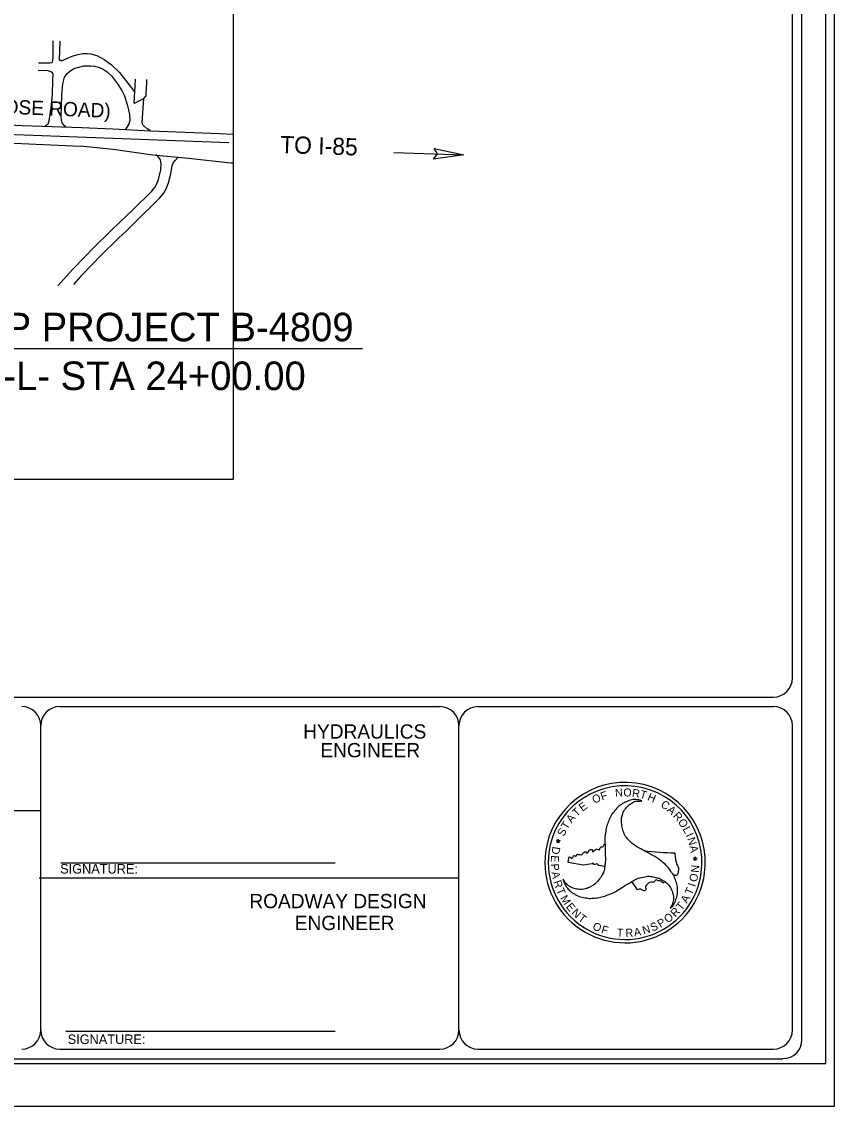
# Model space of a CAD drawing. Extents: x 1530800 to 1534168, y 642962 to 645162.
# Drawn here: x 1533314 to 1534168, y 642962 to 644102 of the extents above; entities that cross this region are included whole.
import ezdxf

# ---------------------------------------------------------------- set-up
doc = ezdxf.new("R2010")
doc.units = 0
for name, color, linetype in [('Exist Roads EOP', 7, 'Continuous'), ('Exist Roads EOP Other', 7, 'Continuous'), ('Exist Roads Soil', 7, 'Continuous'), ('Old_Level_1', 7, 'Continuous'), ('Old_Level_11', 7, 'Continuous'), ('Old_Level_6', 7, 'Continuous'), ('Prop Horizontal Alignment', 7, 'Continuous'), ('Sheet Cutting Line CELL', 7, 'Continuous'), ('Sheet Plot Border Inside CELL', 7, 'Continuous'), ('Sheet Plot Border Outside CELL', 7, 'Continuous'), ('Sheet Title CELL', 7, 'Continuous')]:
    doc.layers.add(name, color=color, linetype=linetype)

msp = doc.modelspace()

# ---------------------------------------------------------------- linework, layer by layer
at = {"layer": 'Exist Roads EOP'}
for points in [[(1532837.2, 644011.2), (1532887.5, 644009), (1532932.2, 644007.8), (1532979.1, 644006), (1533024.3, 644004.3), (1533074.5, 644002.6), (1533122.3, 644001), (1533169.2, 643999.2), (1533215.3, 643997.3), (1533264.8, 643995.5), (1533315, 643993.2), (1533377.5, 643991.1)], [(1532836.8, 643992.3), (1532887, 643990.3), (1532930.7, 643988.8), (1532978.4, 643986.9), (1533023.5, 643984.9), (1533074.4, 643983.4), (1533120.9, 643981.7), (1533167.8, 643979.8), (1533215.1, 643978), (1533262.8, 643975.9), (1533314, 643974.1), (1533375.9, 643971.4)], [(1533377.5, 643991.1), (1533410.3, 643989.6), (1533449.9, 643987.5)], [(1533449.9, 643987.5), (1533486.1, 643985.9), (1533522.3, 643984.7), (1533535.8, 643984)], [(1533535.8, 643984), (1533535.8, 643984)], [(1533536.6, 643953.4), (1533534, 643953.6), (1533489.7, 643958.4), (1533452.1, 643961.8), (1533410.6, 643967.7), (1533375.9, 643971.4)], [(1533478.9, 643959.8), (1533478.9, 643959.8)]]:
    msp.add_lwpolyline(points, dxfattribs=at)
at = {"layer": 'Exist Roads EOP Other'}
for points in [[(1533432.7, 644016.4), (1533433.6, 644034.9), (1533434, 644041.9)], [(1533442.6, 644021.5), (1533445.2, 644024.1), (1533445.4, 644035.2)], [(1533445.4, 644041.5), (1533445.4, 644035.2)], [(1533438.4, 644019.3), (1533442.6, 644021.5)], [(1533432.7, 644016.4), (1533432.9, 644016.4), (1533438.4, 644019.3)], [(1533535.8, 643984), (1533536.6, 643984.4)], [(1533433.4, 643891.1), (1533459.3, 643916.6), (1533463.4, 643921.6), (1533466.2, 643926.4), (1533468.6, 643932.9), (1533471, 643942.2), (1533471.8, 643946.9), (1533472.6, 643950.6), (1533473.9, 643954.1), (1533475.9, 643956.7), (1533478.9, 643959.8)], [(1533457.8, 643960), (1533455.5, 643962.4)], [(1533458, 643936.2), (1533460.5, 643946.6), (1533460.8, 643952.8), (1533460.2, 643956.9), (1533459.1, 643958.5), (1533457.8, 643960)], [(1533431.2, 643904.5), (1533451, 643924.1), (1533454.2, 643928), (1533456.1, 643931.2), (1533458, 643936.2)], [(1533425, 643898.4), (1533408.6, 643883), (1533388.7, 643863.5), (1533381.4, 643855.9), (1533367.8, 643841.8), (1533352.5, 643824.6)], [(1533425, 643898.4), (1533431.2, 643904.5)], [(1533424, 643882.1), (1533433.4, 643891.1)], [(1533424, 643882.1), (1533416.4, 643874.9), (1533396.7, 643855.6), (1533389.5, 643848.1), (1533376, 643834.2), (1533368.8, 643826.1)]]:
    msp.add_lwpolyline(points, dxfattribs=at)
at = {"layer": 'Exist Roads Soil'}
for points in [[(1533346.4, 644059.1), (1533346.9, 644060), (1533347.2, 644061.3), (1533347.5, 644065.9), (1533347.6, 644081.9)], [(1533355.9, 644061.2), (1533355.4, 644061.3), (1533354.7, 644061.5), (1533354.2, 644061.9), (1533354.8, 644081.7)], [(1533355.9, 644061.2), (1533357.8, 644061.9), (1533363.1, 644064.2), (1533368.6, 644066.3), (1533373.7, 644067.8), (1533378.6, 644068.8), (1533383.2, 644068.9), (1533386.9, 644068.5), (1533393.3, 644066.6), (1533401.2, 644062.4), (1533408.3, 644057.3), (1533417, 644048.7), (1533423.5, 644040.6), (1533428.2, 644034.5), (1533432.5, 644028.8)], [(1533332, 644059), (1533344, 644058.8), (1533346.4, 644059.1)], [(1533369.1, 644052.8), (1533374.4, 644054.3), (1533379.8, 644055.6), (1533383.5, 644055.9), (1533387, 644055.7), (1533391, 644055.3), (1533396.2, 644053.9), (1533399.9, 644052.4), (1533404.3, 644049.4), (1533408.7, 644045.4)], [(1533346.8, 644025.8), (1533347.2, 644041.1), (1533347.4, 644046.8), (1533346.7, 644048.3), (1533344.9, 644049.6), (1533342.1, 644050.5), (1533331.7, 644051)], [(1533360.8, 643991.8), (1533359.2, 643992.6), (1533357.9, 643994.3), (1533356.9, 643996), (1533356.3, 643998.4), (1533356, 644002.5), (1533356.5, 644024.9), (1533357.5, 644036.7), (1533359.3, 644043.8), (1533361.9, 644047.3), (1533364.6, 644049.9), (1533369.1, 644052.8)], [(1533408.7, 644045.4), (1533415.2, 644036.9), (1533419.6, 644029.7), (1533422.6, 644023.6)], [(1533339.2, 643992.6), (1533342.2, 643994.7), (1533343.4, 643998.1), (1533345.5, 644012), (1533346.8, 644025.8)], [(1533423.4, 643988.9), (1533425, 643990.6), (1533426.8, 643994), (1533428.2, 643998.7), (1533427.9, 644004.6), (1533425.8, 644013.8), (1533422.6, 644023.6)], [(1533432.5, 644028.8), (1533433, 644028.1)], [(1533449.9, 643987.5), (1533446.4, 643989.5), (1533443.2, 643992.5), (1533441.8, 643993.9), (1533441.2, 643995.1), (1533440.9, 643996.2), (1533442.6, 644021.5)]]:
    msp.add_lwpolyline(points, dxfattribs=at)
at = {"layer": 'Old_Level_1'}
for p, q in [((1533705.6, 643964.8), (1533779.1, 643962.3)), ((1533672.5, 643758.2), (1533152.9, 643758.2))]:
    msp.add_line(p, q, dxfattribs=at)
at = {"layer": 'Old_Level_11'}
msp.add_lwpolyline([(1533747.8, 643968.8), (1533779.1, 643962.3), (1533747.2, 643957.8), (1533751.4, 643963.2)], close=True, dxfattribs=at)
at = {"layer": 'Old_Level_6'}
msp.add_lwpolyline([(1531841.4, 644402.1), (1533536.6, 644402.1), (1533536.6, 643621.2), (1531841.4, 643621.2)], close=True, dxfattribs=at)
at = {"layer": 'Prop Horizontal Alignment'}
msp.add_line((1531841.4, 644038.2), (1533531.9, 643975.1), dxfattribs=at)
at = {"layer": 'Sheet Cutting Line CELL'}
msp.add_line((1530800.4, 642962.3), (1534168.4, 642962.3), dxfattribs=at)
at = {"layer": 'Sheet Plot Border Inside CELL'}
msp.add_lwpolyline([(1530826.4, 643007.2), (1534159.4, 643007.2), (1534159.4, 645117.4), (1530826.4, 645117.4)], close=True, dxfattribs=at)
at = {"layer": 'Sheet Plot Border Outside CELL'}
for p, q in [((1534168.4, 642962.3), (1534168.4, 645162.3)), ((1530800.4, 642962.3), (1534168.4, 642962.3))]:
    msp.add_line(p, q, dxfattribs=at)
at = {"layer": 'Sheet Title CELL'}
for p, q in [((1531264.4, 643392.3), (1534104.4, 643392.3)), ((1533354.4, 643382.3), (1533753.9, 643382.3)), ((1533793.9, 643382.3), (1534104.4, 643382.3)), ((1533334.4, 643042.3), (1533334.4, 643362.3)), ((1533773.9, 643042.3), (1533773.9, 643362.3)), ((1533966.2, 643283.5), (1533966, 643283.4)), ((1533966.2, 643283.5), (1533966, 643283.4)), ((1533334.4, 643272.8), (1532724.4, 643272.8)), ((1533877.3, 643241), (1533876.3, 643242)), ((1533876.3, 643242), (1533877.7, 643241.8)), ((1533876.7, 643239.6), (1533877.3, 643241)), ((1533878, 643240.3), (1533876.7, 643239.6)), ((1533877.7, 643241.8), (1533878.3, 643243.1)), ((1533879, 643239.3), (1533878, 643240.3)), ((1533878.3, 643243.1), (1533878.6, 643241.7)), ((1533878.6, 643241.7), (1533880.1, 643241.5)), ((1533880.1, 643241.5), (1533878.8, 643240.8)), ((1533878.8, 643240.8), (1533879, 643239.3)), ((1533888.5, 643218.4), (1533889.4, 643223.4)), ((1533968.3, 643231), (1533968.3, 643231)), ((1534021.8, 643223.1), (1534020.4, 643223.3)), ((1534020.4, 643223.3), (1534021.5, 643222.3)), ((1534022.5, 643224.4), (1534021.8, 643223.1)), ((1534022.8, 643223), (1534022.5, 643224.4)), ((1534024.2, 643222.8), (1534022.8, 643223)), ((1534022.9, 643222.1), (1534024.2, 643222.8)), ((1533355.4, 643218.3), (1533643.9, 643218.3)), ((1533904.3, 643215.7), (1533888.5, 643218.4)), ((1533913.8, 643217.2), (1533904.3, 643215.7)), ((1533927.2, 643214.3), (1533920.6, 643215.2)), ((1534021.5, 643222.3), (1534020.9, 643220.9)), ((1534020.9, 643220.9), (1534022.1, 643221.6)), ((1534022.1, 643221.6), (1534023.1, 643220.6)), ((1534023.1, 643220.6), (1534022.9, 643222.1)), ((1533332.6, 643202.3), (1533773.9, 643202.3)), ((1534032.1, 643207.3), (1534032.1, 643207.3)), ((1533961.6, 643189.9), (1533955.6, 643198.5)), ((1533955.6, 643198.5), (1533955.6, 643198.5)), ((1533360.9, 643041.2), (1533643.9, 643041.2))]:
    msp.add_line(p, q, dxfattribs=at)
for points in [[(1534134.4, 643032.3), (1534134.4, 645092.3)], [(1534124.4, 643412.3), (1534124.4, 645082.3)], [(1534124.4, 643042.3), (1534124.4, 643362.3)], [(1533354.4, 643022.3), (1533753.9, 643022.3)], [(1533793.9, 643022.3), (1534104.4, 643022.3)], [(1531154.4, 643012.3), (1534114.4, 643012.3)]]:
    msp.add_lwpolyline(points, dxfattribs=at)
for centre, radius, start, end in [((1534104.4, 643412.4), 20, 270, 360), ((1533314.4, 643362.4), 20, 0, 90), ((1533354.4, 643362.4), 20, 90, 180), ((1533753.9, 643362.3), 20, 0, 90), ((1533793.9, 643362.3), 20, 90, 180), ((1534104.4, 643362.4), 20, 0, 90), ((1533948.5, 643218.4), 84.3, 352.4211, 172.4211), ((1533948.5, 643218.4), 80.8, 352.4211, 172.4211), ((1534018.3, 643672.9), 444.7, 258.0996, 258.1992), ((1533948.5, 643218.4), 84.3, 172.4211, 352.4211), ((1533948.5, 643218.4), 80.8, 172.4211, 352.4211), ((1534018.3, 643672.9), 444.7, 263.5387, 267.7447), ((1533314.4, 643042.4), 20, 270, 360), ((1533354.4, 643042.4), 20, 180, 270), ((1533753.9, 643042.4), 20, 270, 360), ((1533793.9, 643042.4), 20, 180, 270), ((1534104.4, 643042.4), 20, 270, 360), ((1534114.4, 643032.4), 20, 270, 360)]:
    msp.add_arc(centre, radius, start, end, dxfattribs=at)
for points in [[(1533966, 643283.4), (1533964.2, 643284.1), (1533958.6, 643284.6), (1533952.7, 643283.6), (1533952.2, 643283.3), (1533949.2, 643282.2), (1533945.9, 643280.4), (1533940.8, 643276.7), (1533936.6, 643271.9), (1533934.9, 643269.8), (1533933.5, 643267.2), (1533930.9, 643261.5), (1533929.1, 643256), (1533927.9, 643249.4), (1533927.2, 643243.5), (1533927.4, 643237.4), (1533927.6, 643231.2), (1533927.7, 643225.3), (1533927.7, 643219.1), (1533926.9, 643213.2), (1533926.9, 643212.6), (1533924.9, 643206.4), (1533921.6, 643201.2), (1533917.7, 643196.9), (1533915.4, 643195), (1533912.3, 643193.2), (1533910.6, 643192.2), (1533906.5, 643190.8), (1533900.6, 643190.2), (1533895.1, 643191.3), (1533890.3, 643193.2), (1533886.3, 643196.6), (1533883.4, 643201)], [(1533996, 643170.7), (1533997.5, 643171.8), (1534000.8, 643176.4), (1534002.8, 643182.1), (1534003, 643182.6), (1534003.5, 643185.8), (1534003.5, 643189.6), (1534003, 643195.9), (1534000.8, 643201.8), (1533999.9, 643204.4), (1533998.3, 643206.9), (1533994.7, 643212), (1533990.8, 643216.3), (1533985.6, 643220.7), (1533980.9, 643224.1), (1533975.5, 643227.1), (1533970.1, 643230), (1533964.9, 643232.9), (1533959.5, 643235.9), (1533954.8, 643239.6), (1533954.4, 643240), (1533949.9, 643244.7), (1533947, 643250.2), (1533945.3, 643255.7), (1533944.9, 643258.6), (1533944.8, 643262.2), (1533944.7, 643264.3), (1533945.6, 643268.5), (1533948, 643273.9), (1533951.7, 643278.1), (1533955.8, 643281.3), (1533960.7, 643283.1), (1533966, 643283.4), (1533966.2, 643283.5)], [(1533889.4, 643223.4), (1533889.3, 643223.9), (1533890.2, 643224.4), (1533892.4, 643223.1), (1533893.7, 643223.9), (1533893.8, 643225), (1533894.9, 643225.9), (1533896.5, 643225.3), (1533898.2, 643227), (1533899.5, 643227.1), (1533902.4, 643226.7), (1533906.2, 643229.7), (1533907.6, 643229.7), (1533907.8, 643228.7), (1533908.7, 643228.5), (1533910.5, 643231), (1533910.9, 643231.4), (1533913.7, 643232.1), (1533914.3, 643231.5), (1533914.3, 643230.2), (1533914.7, 643229.9), (1533915.6, 643230.4), (1533917, 643231.8), (1533919.3, 643232.6), (1533921.7, 643232), (1533922.4, 643233.9), (1533925.5, 643235.5), (1533926.3, 643236.6), (1533926.6, 643237.7)], [(1533927.4, 643237.5), (1533927.4, 643237.4), (1533927.6, 643231.2), (1533927.7, 643225.3), (1533927.7, 643219.1), (1533927.2, 643214.3)], [(1533999.4, 643205.3), (1533998.3, 643206.9), (1533994.7, 643212), (1533990.8, 643216.3), (1533985.6, 643220.7), (1533980.9, 643224.1), (1533975.5, 643227.1), (1533970.1, 643230), (1533968.3, 643231)], [(1534000.8, 643228.5), (1534001.3, 643222.7), (1534003.3, 643215.8), (1534004.7, 643211.9), (1534004.3, 643208.9), (1534003, 643205.3), (1533999.4, 643205.4)], [(1533920.6, 643215.2), (1533920.1, 643216.5), (1533918.9, 643217.1), (1533917, 643216.4), (1533915.7, 643216.6), (1533914.4, 643217.9), (1533913.8, 643217.2)], [(1533883.4, 643201), (1533883.7, 643199.1), (1533886.1, 643194), (1533889.9, 643189.4), (1533890.3, 643189.1), (1533892.8, 643186.9), (1533896.1, 643185), (1533901.8, 643182.4), (1533908, 643181.3), (1533910.7, 643180.8), (1533913.8, 643180.9), (1533919.9, 643181.5), (1533925.5, 643182.7), (1533931.9, 643185), (1533937.3, 643187.3), (1533942.5, 643190.5), (1533947.7, 643193.9), (1533952.9, 643196.9), (1533958.2, 643199.9), (1533963.7, 643202.3), (1533964.3, 643202.4), (1533970.7, 643203.9), (1533976.8, 643203.7), (1533982.4, 643202.4), (1533985.3, 643201.4), (1533988.3, 643199.6), (1533990.2, 643198.6), (1533993.4, 643195.8), (1533996.8, 643191), (1533998.7, 643185.7), (1533999.4, 643180.5), (1533998.4, 643175.4), (1533996, 643170.7)], [(1533955.6, 643198.5), (1533958.2, 643199.9), (1533963.7, 643202.3), (1533964.3, 643202.4), (1533970.7, 643203.9), (1533976.8, 643203.7), (1533982.4, 643202.4), (1533985.3, 643201.4), (1533988.3, 643199.6), (1533990, 643198.7)], [(1533990, 643198.6), (1533989, 643197.3), (1533987.8, 643197.4), (1533985.8, 643199.4), (1533983, 643199.2), (1533981.9, 643200.1), (1533981.1, 643200.2), (1533978.8, 643198), (1533976, 643197.8), (1533971.3, 643195.2), (1533970.1, 643193.4), (1533969.9, 643189.4), (1533968.7, 643188.7), (1533967.5, 643189.1), (1533964.9, 643190.5), (1533961.6, 643189.9)]]:
    msp.add_spline(points, degree=3, dxfattribs=at)

# ---------------------------------------------------------------- texts
at = {"layer": 'Old_Level_1'}
for s, height, rotation, p in [('-L-  SR 1308 (MOOSE ROAD)', 15, 357.7581, (1533137, 644011.7)), ('TO I-85', 18, 358.1007, (1533585.7, 643964.2)), ('END TIP PROJECT B-4809', 30, 360, (1533166, 643766.3)), ('-L- STA 24+00.00', 30, 360, (1533295.1, 643715))]:
    msp.add_text(s, height=height, rotation=rotation, dxfattribs=at).set_placement(p)
at = {"layer": 'Sheet Title CELL'}
for s, height, p in [(' HYDRAULICS', 15, (1533604.7, 643348.7)), ('ENGINEER', 15, (1533628.3, 643329.1)), ('SIGNATURE:', 10, (1533354.8, 643206.9)), ('ROADWAY DESIGN', 14.999, (1533553.7, 643170.5)), ('ENGINEER', 15, (1533601.4, 643147.5)), ('SIGNATURE:', 10, (1533362.7, 643027.8))]:
    msp.add_text(s, height=height, dxfattribs=at).set_placement(p)
for s, height, rotation, p in [('F', 8.43, 17.4918, (1533924.2, 643283.7)), ('N', 8.41, 5.4049, (1533938.3, 643287.4)), ('O', 8.43, 357.9068, (1533946.5, 643288.1)), ('R', 8.41, 351.2969, (1533955.4, 643287.8)), ('T', 8.43, 344.6472, (1533963.4, 643286.6)), ('H', 8.4, 337.5625, (1533971.3, 643284.3)), ('E', 8.38, 36.5781, (1533903.7, 643271.8)), ('O', 8.42, 24.6387, (1533916.1, 643280.1)), ('C', 8.39, 325.2202, (1533985.1, 643277.8)), ('A', 8.44, 50.7489, (1533892.2, 643259.4)), ('T', 8.39, 43.6937, (1533897.7, 643266.1)), ('A', 8.4, 317.7231, (1533991.9, 643273)), ('R', 8.4, 311.3592, (1533998.3, 643267.2)), ('T', 8.43, 57.8012, (1533887.7, 643252.5)), ('O', 8.43, 304.2396, (1534003.6, 643261.1)), ('L', 8.39, 298.0059, (1534008.7, 643253.7)), ('S', 8.4, 64.1774, (1533884.2, 643245.3)), ('I', 8.42, 294.0166, (1534011.9, 643247.3)), ('N', 8.41, 288.3165, (1534013.6, 643243.5)), ('D', 8.41, 260.2741, (1533872.3, 643235.8)), ('A', 8.41, 280.8845, (1534016.1, 643235.6)), ('E', 8.37, 266.562, (1533870.8, 643226.3)), ('P', 8.41, 274.0944, (1533870.4, 643217.1)), ('N', 8.41, 84.6293, (1534025.9, 643207.5)), ('A', 8.4, 280.687, (1533871.1, 643208.2)), ('R', 8.41, 287.7556, (1533873, 643198.4)), ('O', 8.38, 77.3812, (1534023.8, 643197.5)), ('T', 8.4, 294.4062, (1533875.9, 643189.6)), ('T', 8.4, 66.5957, (1534018.5, 643183.6)), ('I', 8.43, 72.2456, (1534022.2, 643192.4)), ('M', 8.39, 301.6412, (1533880, 643181)), ('T', 8.38, 51.4242, (1534007.7, 643167.4)), ('A', 8.43, 59.5113, (1534013.5, 643175)), ('E', 8.39, 309.108, (1533885.8, 643171.9)), ('N', 8.43, 316.0795, (1533891.6, 643165)), ('R', 8.42, 45.3245, (1534001.2, 643160.7)), ('T', 8.4, 322.9215, (1533898.5, 643158.4)), ('O', 8.41, 336.2252, (1533913.5, 643148.6)), ('S', 8.37, 24.2515, (1533977.2, 643145.8)), ('P', 8.41, 31.4434, (1533985.6, 643149.6)), ('O', 8.43, 38.1354, (1533993.3, 643154.4)), ('F', 8.4, 343.3904, (1533922.8, 643144.6)), ('T', 8.38, 356.2997, (1533939.6, 643140.8)), ('R', 8.42, 3.2563, (1533949.1, 643140.3)), ('A', 8.38, 10.0094, (1533958.4, 643140.9)), ('N', 8.38, 17.041, (1533968.1, 643142.8))]:
    msp.add_text(s, height=height, rotation=rotation, dxfattribs=at).set_placement(p)

doc.saveas('drawing.dxf')
